Omron CX-Programmer project NewProject (CX-Programmer 8.02)

# PLC NewPLC1: CJ1M CPU11
I/O table (CPU CJ1M-CPU11): rack 0 slot 0 CJ1W-ID211; rack 0 slot 1 CJ1W-OC211; rack 0 slot 2 CJ1W-EIP21

## Program NewProgram1 (cyclic task 0)

### Section Section1

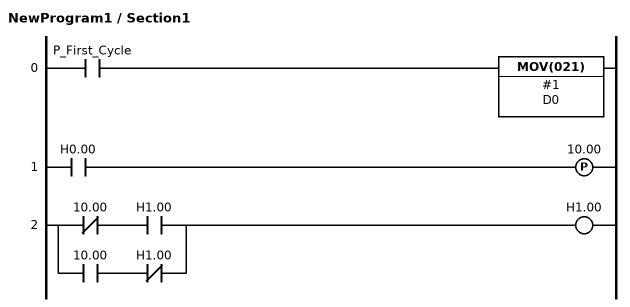
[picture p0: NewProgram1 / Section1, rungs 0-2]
; rung 0
LD P_First_Cycle
MOV(021) #1 D0
; rung 1
LD H0.00
DIFU(013) 10.00
; rung 2
LDNOT 10.00
AND H1.00
LD 10.00
ANDNOT H1.00
ORLD
OUT H1.00

### Section END
; rung 0
END(001)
